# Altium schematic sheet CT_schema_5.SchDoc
size 469 x 430 mm
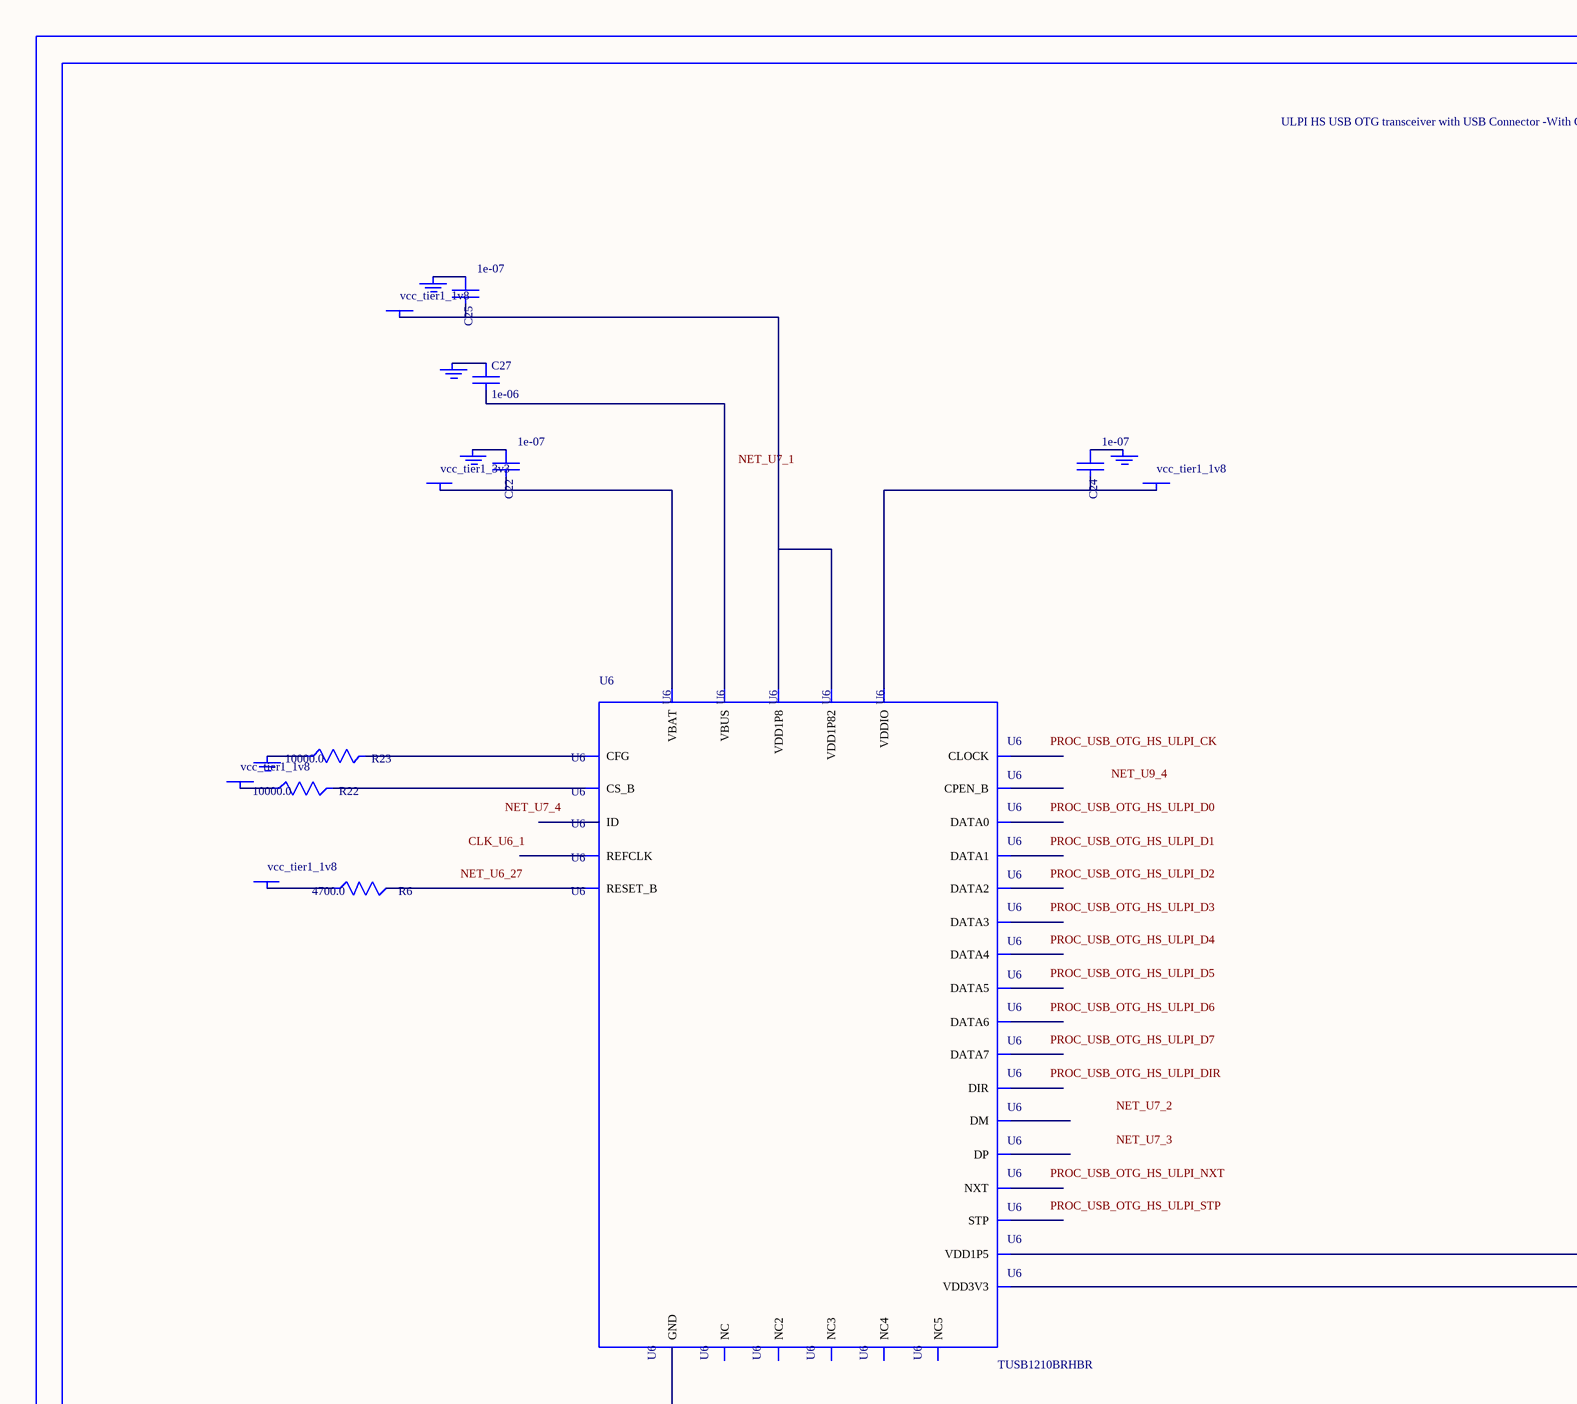
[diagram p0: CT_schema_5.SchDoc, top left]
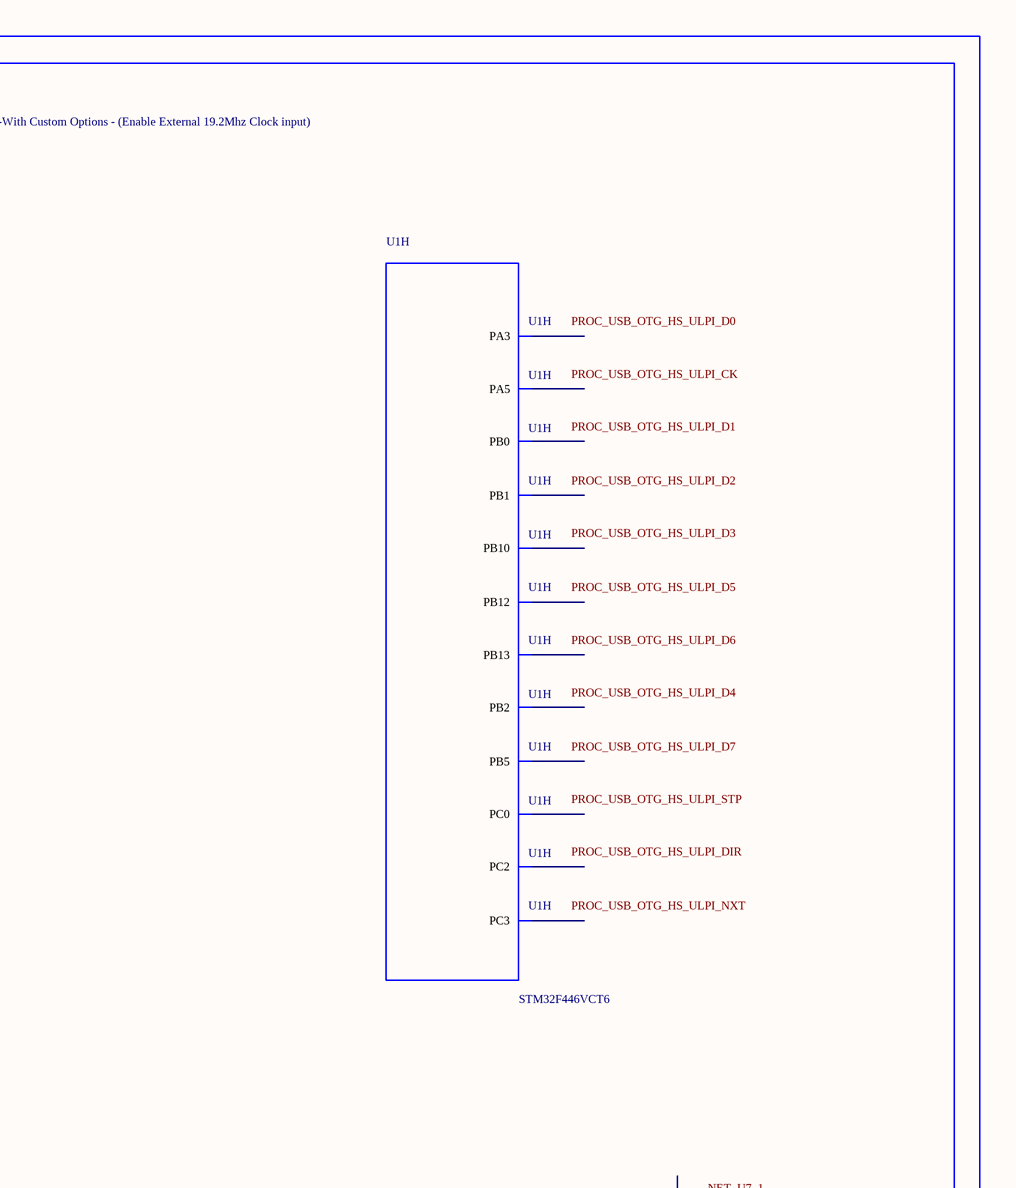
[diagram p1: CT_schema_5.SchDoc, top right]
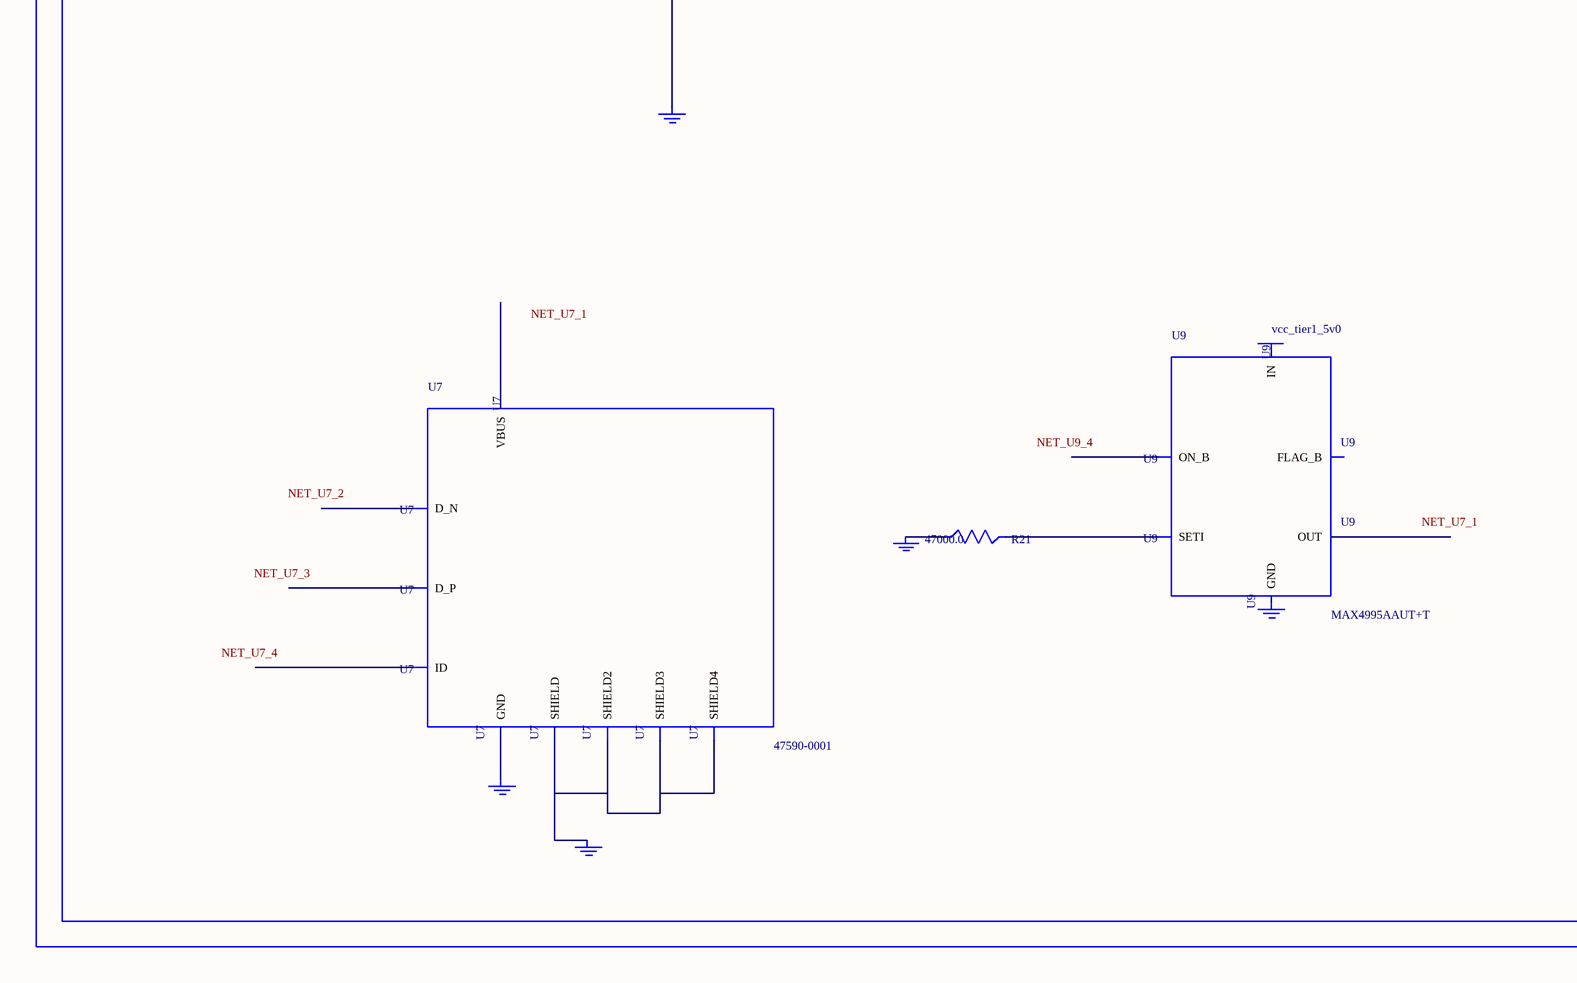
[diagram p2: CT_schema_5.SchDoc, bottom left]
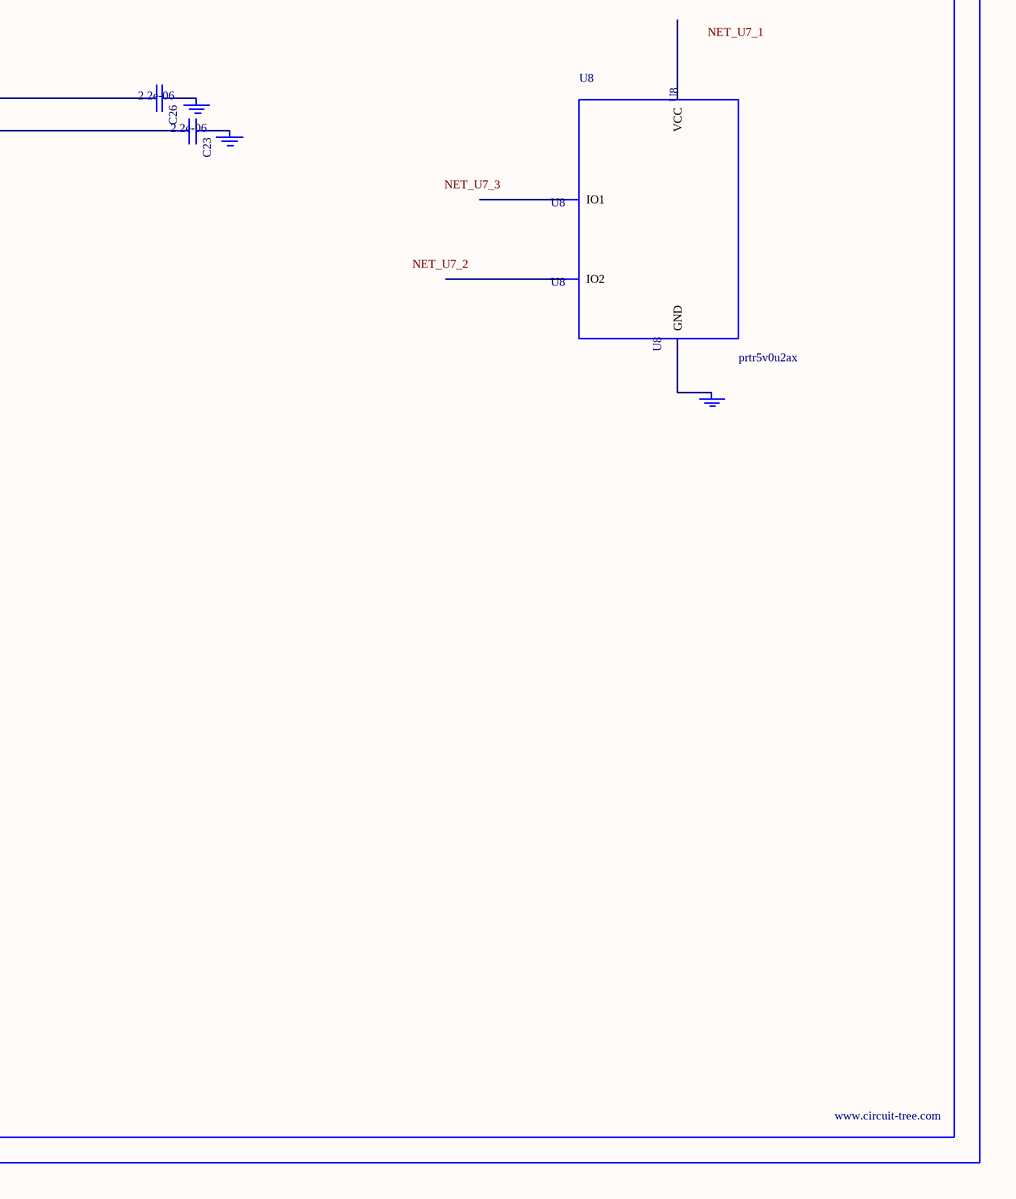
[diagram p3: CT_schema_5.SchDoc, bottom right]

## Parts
BORDER4  (no value)
C22  1e-07  [C0402]
C23  2.2e-06  [C0603]
C24  1e-07  [C0402]
C25  1e-07  [C0402]
C26  2.2e-06  [C0603]
C27  1e-06  [C0603]
GND_INSTANCE_4_0  (no value)
GND_INSTANCE_4_1  (no value)
GND_INSTANCE_4_2  (no value)
GND_INSTANCE_4_3  (no value)
GND_INSTANCE_4_4  (no value)
GND_INSTANCE_4_5  (no value)
GND_INSTANCE_4_6  (no value)
GND_INSTANCE_4_7  (no value)
GND_INSTANCE_4_8  (no value)
GND_INSTANCE_4_9  (no value)
GND_INSTANCE_4_10  (no value)
GND_INSTANCE_4_11  (no value)
GND_INSTANCE_4_12  (no value)
POWER_INSTANCE_4_0  vcc_tier1_1v8
POWER_INSTANCE_4_1  vcc_tier1_3v3
POWER_INSTANCE_4_2  vcc_tier1_1v8
POWER_INSTANCE_4_3  vcc_tier1_1v8
POWER_INSTANCE_4_4  vcc_tier1_1v8
POWER_INSTANCE_4_5  vcc_tier1_5v0
R6  4700.0  [R0603]
R21  47000.0  [R0603]
R22  10000.0  [R0603]
R23  10000.0  [R0603]
U1  STM32F446VCT6  [LQFP100]  (part H of 9)
U6  TUSB1210BRHBR  [RHB32_3P45X3P45]
U7  47590-0001  [MICRO_USB_AB]
U8  prtr5v0u2ax  [SOT143B]
U9  MAX4995AAUT+T  [SOT-23-6]

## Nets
NetC22_1: C22.1 GND_INSTANCE_4_3.0(GND)
NetC22_2: C22.2 POWER_INSTANCE_4_1.0(PWR) U6.21(VBAT)
NetC23_1: C23.1 GND_INSTANCE_4_2.0(GND)
NetC23_2: C23.2 U6.20(VDD3V3)
NetC24_1: C24.1 GND_INSTANCE_4_6.0(GND)
NetC24_2: C24.2 POWER_INSTANCE_4_3.0(PWR) U6.32(VDDIO)
NetC25_1: C25.1 GND_INSTANCE_4_5.0(GND)
NetC25_2: C25.2 POWER_INSTANCE_4_2.0(PWR) U6.28(VDD1P8) U6.30(VDD1P82)
NetC26_1: C26.1 GND_INSTANCE_4_0.0(GND)
NetC26_2: C26.2 U6.12(VDD1P5)
NetC27_1: C27.1 GND_INSTANCE_4_4.0(GND)
NetC27_2: C27.2 U6.22(VBUS)
NetGND_INSTANCE_4_1_0: GND_INSTANCE_4_1.0(GND) R23.1
NetGND_INSTANCE_4_7_0: GND_INSTANCE_4_7.0(GND) U6.33(GND)
NetGND_INSTANCE_4_8_0: GND_INSTANCE_4_8.0(GND) U7.6(SHIELD) U7.7(SHIELD2) U7.8(SHIELD3) U7.9(SHIELD4)
NetGND_INSTANCE_4_9_0: GND_INSTANCE_4_9.0(GND) U7.5(GND)
NetGND_INSTANCE_4_10_0: GND_INSTANCE_4_10.0(GND) U8.1(GND)
NetGND_INSTANCE_4_11_0: GND_INSTANCE_4_11.0(GND) R21.1
NetPOWER_INSTANCE_4_0_0: POWER_INSTANCE_4_0.0(PWR) R22.1
NetPOWER_INSTANCE_4_4_0: POWER_INSTANCE_4_4.0(PWR) R6.1
NetR6_2: R6.2 U6.27(RESET_B)
NetR21_2: R21.2 U9.3(SETI)
NetR22_2: R22.2 U6.11(CS_B)
NetR23_2: R23.2 U6.14(CFG)

Not connected (* = marked no-connect by the designer): GND_INSTANCE_4_12 0(GND); POWER_INSTANCE_4_5 0(PWR); U1 15(PC0) 17(PC2) 18(PC3) 26(PA3) 30(PA5) 35(PB0) 36(PB1) 37(PB2) 47(PB10) 51(PB12) 52(PB13) 91(PB5); U6 1(REFCLK) 2(NXT) 3(DATA0) 4(DATA1) 5(DATA2) 6(DATA3) 7(DATA4) 8(NC) 9(DATA5) 10(DATA6) 13(DATA7) 15(NC2) 16(NC3) 17(CPEN_B) 18(DP) 19(DM) 23(ID) 24(NC4) 25(NC5) 26(CLOCK) 29(STP) 31(DIR); U7 1(VBUS) 2(D_N) 3(D_P) 4(ID); U8 2(IO1) 3(IO2) 4(VCC); U9 1(OUT) 2(GND) 4(ON_B) 5(IN) 6(FLAG_B)

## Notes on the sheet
- Labels drawn without touching a wire or pin: CLK_U6_1, NET_U6_27, NET_U7_1, NET_U7_2, NET_U7_3, NET_U7_4, NET_U9_4, PROC_USB_OTG_HS_ULPI_CK, PROC_USB_OTG_HS_ULPI_D0, PROC_USB_OTG_HS_ULPI_D1, PROC_USB_OTG_HS_ULPI_D2, PROC_USB_OTG_HS_ULPI_D3, PROC_USB_OTG_HS_ULPI_D4, PROC_USB_OTG_HS_ULPI_D5, PROC_USB_OTG_HS_ULPI_D6, PROC_USB_OTG_HS_ULPI_D7, PROC_USB_OTG_HS_ULPI_DIR, PROC_USB_OTG_HS_ULPI_NXT, PROC_USB_OTG_HS_ULPI_STP

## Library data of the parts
BORDER4 = BORDER_PAGE4
C22 C24 C25 = C0402C104K3RACTU
C23 C26 = C0603C225K8RACTU
C27 = C0603C105K3RACTU
GND_INSTANCE_4_0-GND_INSTANCE_4_12 = GND
POWER_INSTANCE_4_0-POWER_INSTANCE_4_5 = PWR
R6 = RC0603JR-074K7L
R21 = RC0603JR-0747KL
R22 R23 = RC0603JR-0710KL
